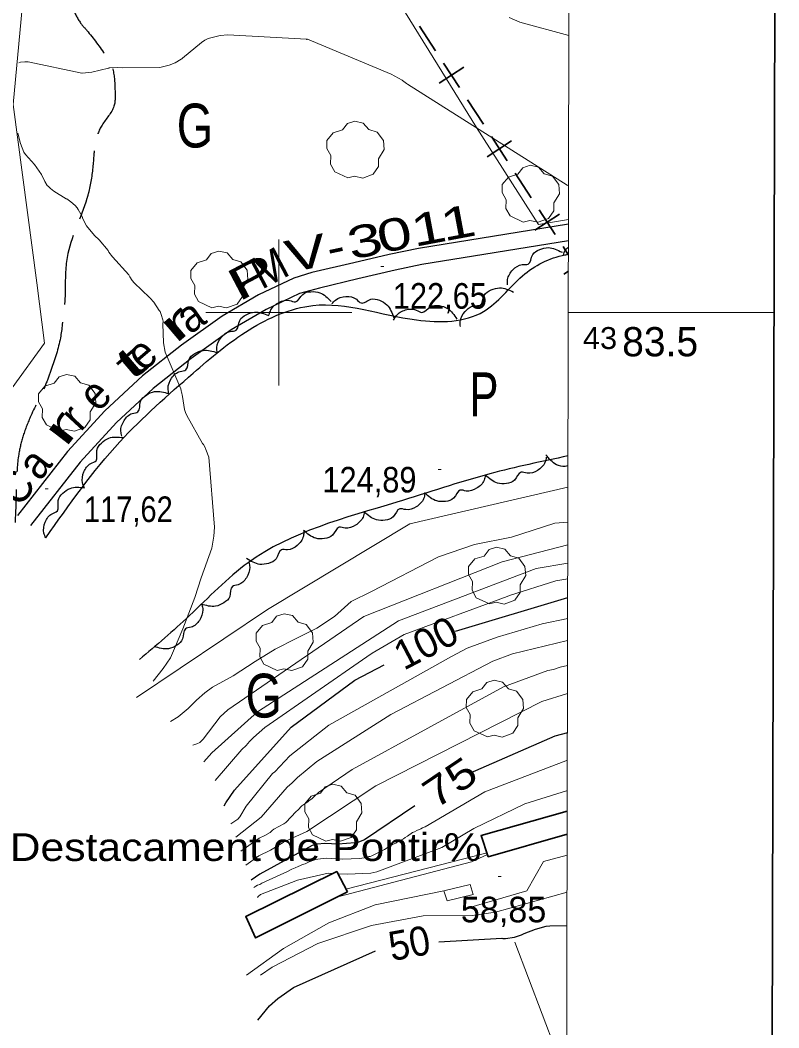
# Model space of a CAD drawing. Extents: x 480264 to 484872, y 4381275 to 4384491.
# Drawn here: x 483911.4 to 484171.3, y 4383255.2 to 4383600 of the extents above; entities that cross this region are included whole.
import ezdxf
from ezdxf.enums import TextEntityAlignment as Align

# ---------------------------------------------------------------- set-up
doc = ezdxf.new("R2010")
doc.units = 0
doc.header["$LTSCALE"] = 4
doc.linetypes.add('DOTTED', pattern=[1.5, 0.3, -1.2])
doc.linetypes.add('LONG_DASHED', pattern=[7.5, 6, -1.5])
for name, color, linetype, lineweight in [('1', 7, 'Continuous', 13), ('2', 7, 'DOTTED', 13), ('27', 7, 'Continuous', 25), ('29', 7, 'Continuous', 13), ('34', 7, 'Continuous', 35), ('36', 7, 'Continuous', 25), ('38', 7, 'Continuous', 25), ('47', 7, 'Continuous', 13), ('51', 7, 'Continuous', 13), ('7', 7, 'Continuous', 13), ('8', 7, 'Continuous', 25), ('9', 7, 'Continuous', 13)]:
    doc.layers.add(name, color=color, linetype=linetype, lineweight=lineweight)
doc.layers.add('31', color=7, linetype='Continuous')
doc.layers.add('5', color=7, linetype='Continuous')

msp = doc.modelspace()

# ---------------------------------------------------------------- linework, layer by layer
at = {"layer": '1'}
for p, q in [((484000, 4383525), (484000, 4383475)), ((483975, 4383500), (484025, 4383500)), ((484099.15, 4383500), (484169.58, 4383500))]:
    msp.add_line(p, q, dxfattribs=at)
at = {"layer": '1', "lineweight": 35}
msp.add_lwpolyline([(480452.76, 4384215.91), (484171.26, 4384207.08), (484165.43, 4381752.09), (480446.93, 4381760.92)], close=True, dxfattribs=at)
at = {"layer": '1'}
msp.add_lwpolyline([(480523.1, 4384144.4), (484100.5, 4384135.8), (484095.6, 4381823.6), (480517.1, 4381832.1)], close=True, dxfattribs=at)
at = {"layer": '27'}
for points in [[(484078.35, 4383509.47), (484078.34, 4383511.25), (484080.15, 4383514.58), (484083.37, 4383516.38), (484085.41, 4383516.59), (484086.94, 4383519.79), (484089.34, 4383521.57), (484092.3, 4383522.2), (484096.99, 4383520.59)], [(484097.47, 4383519.6), (484098.05, 4383521.28), (484099.2, 4383522.32)], [(483920.18, 4383422.86), (483945.58, 4383455.77), (483970.66, 4383479.23), (483989.85, 4383494.1), (484011.67, 4383502.39), (484047.15, 4383497.46), (484070.13, 4383500.35), (484083.46, 4383512.52), (484097.99, 4383519.71), (484099.19, 4383519.92)], [(483996.7, 4383499.2), (483997.27, 4383500.89), (484000.05, 4383503.46), (484003.68, 4383504.12), (484005.68, 4383503.66), (484008.17, 4383506.2), (484011.01, 4383507.12), (484014.01, 4383506.75), (484017.93, 4383503.71)], [(484062.19, 4383495.18), (484062.11, 4383496.95), (484063.78, 4383500.35), (484066.93, 4383502.28), (484068.96, 4383502.56), (484070.37, 4383505.83), (484072.69, 4383507.7), (484075.63, 4383508.44), (484080.37, 4383507.01)], [(484018.15, 4383502.95), (484019.37, 4383504.24), (484022.97, 4383505.43), (484026.55, 4383504.51), (484028.17, 4383503.26), (484031.49, 4383504.53), (484034.46, 4383504.18), (484037.03, 4383502.6), (484039.33, 4383498.2)], [(483978.95, 4383486.2), (483978.78, 4383487.97), (483980.28, 4383491.45), (483983.33, 4383493.53), (483985.35, 4383493.92), (483986.59, 4383497.25), (483988.82, 4383499.23), (483991.71, 4383500.12), (483996.53, 4383498.92)], [(484039.3, 4383497.32), (484040.17, 4383498.87), (484043.4, 4383500.87), (484047.09, 4383500.82), (484048.97, 4383499.98), (484051.89, 4383502), (484054.86, 4383502.35), (484057.73, 4383501.42), (484061, 4383497.69)], [(483962.35, 4383472.21), (483962.05, 4383473.96), (483963.29, 4383477.55), (483966.18, 4383479.85), (483968.17, 4383480.38), (483969.16, 4383483.8), (483971.23, 4383485.94), (483974.05, 4383487.04), (483978.94, 4383486.21)], [(483946.26, 4383457.67), (483945.89, 4383459.4), (483947, 4383463.03), (483949.8, 4383465.43), (483951.76, 4383466.04), (483952.62, 4383469.49), (483954.62, 4383471.71), (483957.39, 4383472.91), (483962.31, 4383472.26)], [(483933.44, 4383440.04), (483932.78, 4383441.69), (483933.23, 4383445.45), (483935.57, 4383448.31), (483937.4, 4383449.25), (483937.65, 4383452.79), (483939.23, 4383455.33), (483941.75, 4383456.99), (483946.7, 4383457.21)], [(484099.05, 4383450.9), (484072.28, 4383444.78), (484040.38, 4383435.09), (483989.49, 4383414.37), (483969.38, 4383396.25), (483952.24, 4383381.2)], [(484091.6, 4383450.43), (484091.16, 4383448.71), (484088.58, 4383445.93), (484085, 4383445), (484082.97, 4383445.31), (484080.69, 4383442.59), (484077.92, 4383441.47), (484074.9, 4383441.61), (484070.76, 4383444.35)], [(484099.04, 4383447.48), (484098.04, 4383447.26), (484095.09, 4383447.9), (484091.46, 4383451.29)], [(484070.77, 4383444.34), (484070.34, 4383442.61), (484067.75, 4383439.83), (484064.18, 4383438.9), (484062.15, 4383439.21), (484059.87, 4383436.49), (484057.1, 4383435.36), (484054.08, 4383435.5), (484049.94, 4383438.23)], [(483920.18, 4383422.86), (483919.52, 4383424.51), (483919.97, 4383428.27), (483922.32, 4383431.13), (483924.14, 4383432.07), (483924.39, 4383435.62), (483925.97, 4383438.15), (483928.49, 4383439.81), (483933.45, 4383440.03)], [(484050.01, 4383438.01), (484049.59, 4383436.28), (484047.04, 4383433.48), (484043.47, 4383432.52), (484041.44, 4383432.81), (484039.18, 4383430.07), (484036.43, 4383428.92), (484033.4, 4383429.03), (484029.24, 4383431.72)], [(484029.25, 4383431.71), (484028.83, 4383429.99), (484026.27, 4383427.19), (484022.71, 4383426.22), (484020.68, 4383426.51), (484018.41, 4383423.77), (484015.66, 4383422.62), (484012.64, 4383422.73), (484008.48, 4383425.43)], [(484008.54, 4383425.2), (484008.39, 4383423.43), (484006.29, 4383420.27), (484002.92, 4383418.78), (484000.86, 4383418.76), (483999.04, 4383415.7), (483996.49, 4383414.15), (483993.49, 4383413.8), (483988.97, 4383415.83)], [(483989.7, 4383414.56), (483990.04, 4383412.82), (483988.89, 4383409.2), (483986.05, 4383406.84), (483984.08, 4383406.26), (483983.17, 4383402.82), (483981.15, 4383400.63), (483978.36, 4383399.47), (483973.45, 4383400.18)], [(483973.63, 4383399.98), (483973.96, 4383398.24), (483972.79, 4383394.63), (483969.95, 4383392.28), (483967.98, 4383391.7), (483967.05, 4383388.27), (483965.02, 4383386.09), (483962.22, 4383384.94), (483957.32, 4383385.67)]]:
    msp.add_spline(points, degree=3, dxfattribs=at)
at = {"layer": '29'}
for points in [[(484023.66, 4383546.07), (484019.12, 4383548.19), (484017.71, 4383550.73), (484017.81, 4383553.71), (484016.44, 4383556.12), (484016.48, 4383558.87), (484018.64, 4383561.47), (484021.83, 4383562.47), (484023.48, 4383564.66), (484026.05, 4383565.49), (484028.91, 4383564.84), (484030.86, 4383562.57), (484033.67, 4383561.75), (484035.8, 4383558.9), (484036.04, 4383555.77), (484034.16, 4383552.62), (484034.16, 4383549.94), (484032.34, 4383547.33), (484028.72, 4383545.99), (484025.95, 4383546.62)], [(484083.72, 4383530.96), (484079.18, 4383533.08), (484077.77, 4383535.62), (484077.87, 4383538.6), (484076.5, 4383541.01), (484076.54, 4383543.76), (484078.7, 4383546.36), (484081.89, 4383547.36), (484083.54, 4383549.55), (484086.11, 4383550.38), (484088.97, 4383549.73), (484090.92, 4383547.46), (484093.73, 4383546.64), (484095.86, 4383543.79), (484096.1, 4383540.66), (484094.22, 4383537.51), (484094.22, 4383534.83), (484092.4, 4383532.22), (484088.78, 4383530.88), (484086.01, 4383531.51)], [(483977.02, 4383501.62), (483972.48, 4383503.74), (483971.07, 4383506.28), (483971.17, 4383509.26), (483969.8, 4383511.67), (483969.84, 4383514.42), (483972, 4383517.02), (483975.19, 4383518.02), (483976.84, 4383520.21), (483979.41, 4383521.04), (483982.27, 4383520.39), (483984.22, 4383518.12), (483987.03, 4383517.3), (483989.16, 4383514.45), (483989.4, 4383511.32), (483987.52, 4383508.17), (483987.52, 4383505.49), (483985.7, 4383502.88), (483982.08, 4383501.54), (483979.31, 4383502.17)], [(483924.91, 4383459.41), (483920.37, 4383461.53), (483918.96, 4383464.07), (483919.06, 4383467.05), (483917.69, 4383469.46), (483917.73, 4383472.21), (483919.89, 4383474.81), (483923.08, 4383475.81), (483924.73, 4383478), (483927.3, 4383478.83), (483930.16, 4383478.18), (483932.11, 4383475.91), (483934.92, 4383475.09), (483937.05, 4383472.24), (483937.29, 4383469.11), (483935.41, 4383465.96), (483935.41, 4383463.28), (483933.59, 4383460.67), (483929.97, 4383459.33), (483927.2, 4383459.96)], [(484072.17, 4383400.26), (484067.63, 4383402.38), (484066.22, 4383404.92), (484066.32, 4383407.9), (484064.95, 4383410.31), (484064.99, 4383413.06), (484067.15, 4383415.66), (484070.34, 4383416.66), (484071.99, 4383418.85), (484074.56, 4383419.68), (484077.42, 4383419.03), (484079.37, 4383416.76), (484082.18, 4383415.94), (484084.31, 4383413.09), (484084.55, 4383409.96), (484082.67, 4383406.81), (484082.67, 4383404.13), (484080.85, 4383401.52), (484077.23, 4383400.18), (484074.46, 4383400.81)], [(483999.4, 4383377.5), (483994.86, 4383379.62), (483993.45, 4383382.16), (483993.55, 4383385.14), (483992.18, 4383387.55), (483992.22, 4383390.3), (483994.38, 4383392.9), (483997.57, 4383393.9), (483999.22, 4383396.09), (484001.79, 4383396.92), (484004.65, 4383396.27), (484006.6, 4383394), (484009.41, 4383393.18), (484011.54, 4383390.33), (484011.78, 4383387.2), (484009.9, 4383384.05), (484009.9, 4383381.37), (484008.08, 4383378.76), (484004.46, 4383377.42), (484001.69, 4383378.05)], [(484071.41, 4383354.75), (484066.87, 4383356.87), (484065.46, 4383359.41), (484065.56, 4383362.39), (484064.19, 4383364.8), (484064.23, 4383367.55), (484066.39, 4383370.15), (484069.58, 4383371.15), (484071.23, 4383373.34), (484073.8, 4383374.17), (484076.66, 4383373.52), (484078.61, 4383371.25), (484081.42, 4383370.43), (484083.55, 4383367.58), (484083.79, 4383364.45), (484081.91, 4383361.3), (484081.91, 4383358.62), (484080.09, 4383356.01), (484076.47, 4383354.67), (484073.7, 4383355.3)], [(484016.08, 4383319.1), (484011.54, 4383321.22), (484010.13, 4383323.76), (484010.23, 4383326.74), (484008.86, 4383329.15), (484008.9, 4383331.9), (484011.06, 4383334.5), (484014.25, 4383335.5), (484015.9, 4383337.69), (484018.47, 4383338.52), (484021.33, 4383337.87), (484023.28, 4383335.6), (484026.09, 4383334.78), (484028.22, 4383331.93), (484028.46, 4383328.8), (484026.58, 4383325.65), (484026.58, 4383322.97), (484024.76, 4383320.36), (484021.14, 4383319.02), (484018.37, 4383319.65)]]:
    msp.add_lwpolyline(points, close=True, dxfattribs=at)
at = {"layer": '34'}
for p, q in [((484048.23, 4383597.95), (484053.68, 4383589.57)), ((484054.95, 4383578.46), (484063.33, 4383583.92)), ((484056.41, 4383585.38), (484061.87, 4383577)), ((484064.6, 4383572.81), (484070.06, 4383564.43)), ((484071.33, 4383553.32), (484079.71, 4383558.78)), ((484072.79, 4383560.24), (484078.25, 4383551.86)), ((484080.97, 4383547.67), (484086.43, 4383539.29)), ((484089.16, 4383535.1), (484094.62, 4383526.72)), ((484087.7, 4383528.18), (484096.08, 4383533.64)), ((484097.35, 4383522.53), (484099, 4383520)), ((484099, 4383520), (484099.19, 4383519.71)), ((484099.18, 4383514.13), (484097.6, 4383513.08))]:
    msp.add_line(p, q, dxfattribs=at)
at = {"layer": '36'}
for points in [[(484099.22, 4383530.22), (484047.89, 4383521.9), (484037.73, 4383519.8), (484025.74, 4383517), (484011.29, 4383513.64), (484005.14, 4383511.78), (483993.08, 4383506.03), (483980.57, 4383498.74), (483966.62, 4383488.78), (483953.28, 4383478.28), (483940.37, 4383466.32), (483927.64, 4383452.44), (483910.51, 4383430.56)], [(484099.2, 4383524.53), (484048.95, 4383516.38), (484039.89, 4383514.47), (484027.04, 4383511.53), (484013.95, 4383508.32), (484007.06, 4383506.47), (483995.7, 4383501.06), (483983.62, 4383494.01), (483969.99, 4383484.28), (483956.93, 4383474), (483944.36, 4383462.35), (483931.92, 4383448.81), (483914.93, 4383427.1)]]:
    msp.add_lwpolyline(points, dxfattribs=at)
at = {"layer": '38', "linetype": 'LONG_DASHED'}
msp.add_spline([(483948.27, 4383681.37), (483947.44, 4383677.16), (483943.11, 4383666.53), (483939.8, 4383660.47), (483937.44, 4383656.41), (483936.14, 4383650.27), (483939.31, 4383645.47), (483946.37, 4383638.42), (483950.03, 4383631.6), (483949.26, 4383627.51), (483946.12, 4383622.55), (483939.76, 4383618.01), (483933.67, 4383615.11), (483929.9, 4383611.7), (483929.15, 4383610.18), (483929.59, 4383603.96), (483932.34, 4383598.76), (483934.21, 4383596.54), (483940.72, 4383587.86), (483942.8, 4383584.16), (483943.86, 4383576.69), (483943.51, 4383570.58), (483939.45, 4383564.12), (483937.16, 4383558.18), (483936.44, 4383551.38), (483935.04, 4383541.91), (483934.28, 4383539.06), (483927.5, 4383518.84), (483926.82, 4383507.52), (483926.68, 4383503.83), (483926.32, 4383500.62), (483925.18, 4383491.33), (483922.04, 4383480.47), (483920.1, 4383475.28), (483915.05, 4383464.63), (483912.46, 4383457.87), (483910.9, 4383451.49), (483910.15, 4383441.41), (483909.68, 4383428.1)], degree=3, dxfattribs=at)
at = {"layer": '47', "lineweight": 35}
msp.add_lwpolyline([(484098.79, 4383329.35), (484069.28, 4383321.02), (484071.75, 4383313.76), (484098.77, 4383321.41)], dxfattribs=at)
msp.add_lwpolyline([(484023.47, 4383301.69), (484019.83, 4383308.63), (483988.65, 4383293.25), (483992.03, 4383285.97)], close=True, dxfattribs=at)
at = {"layer": '47'}
msp.add_lwpolyline([(484066.59, 4383300.86), (484065.5, 4383304.25), (484056.49, 4383302.08), (484057.61, 4383298.67)], close=True, dxfattribs=at)
at = {"layer": '51'}
for p, q in [((484071.31, 4383315.06), (484022.99, 4383302.63)), ((484080.79, 4383284.48), (484098.6, 4383237.73))]:
    msp.add_line(p, q, dxfattribs=at)
for points in [[(483986.74, 4383889), (483957.89, 4383870.69), (483913.72, 4383843.25), (483899.21, 4383834.8), (483923.65, 4383798.71), (483943.24, 4383770.31), (483969.36, 4383729.72), (483989.5, 4383693.34), (484005.24, 4383665.31), (484033, 4383619.4), (484067.74, 4383563.28), (484088.88, 4383530.13), (484099.22, 4383531.84)], [(483923.21, 4383715.44), (483915.26, 4383638.48), (483909.01, 4383571.13), (483917.15, 4383510.19), (483919.72, 4383489.5), (483897.5, 4383458.91)], [(484099.03, 4383440.24), (484044.86, 4383427.62), (483996.17, 4383398.33), (483951.24, 4383368.19)], [(484098.76, 4383314.26), (484090.68, 4383312.1), (484084.99, 4383302.04), (484065, 4383296.24), (484065, 4383296.24)], [(483988.93, 4383273.25), (484001.56, 4383282.35), (484017.09, 4383291.15), (484033.01, 4383297.29), (484056.49, 4383302.08)]]:
    msp.add_lwpolyline(points, dxfattribs=at)
at = {"layer": '7'}
for p, q in [((484034.98, 4383515.69), (484035.98, 4383515.69)), ((484054.58, 4383446.22), (484055.58, 4383446.22)), ((483919.98, 4383439.66), (483920.98, 4383439.66)), ((484075.13, 4383306.99), (484076.13, 4383306.99))]:
    msp.add_line(p, q, dxfattribs=at)
at = {"layer": '8'}
msp.add_line((484060.45, 4383390.94), (484098.95, 4383402.49), dxfattribs=at)
for points in [[(483981.32, 4383331.21), (483981.9, 4383332.22), (483984.79, 4383336.49), (484004.27, 4383358.11), (484025.98, 4383374.16), (484036.09, 4383379.46)], [(484098.85, 4383356.18), (484094.51, 4383355), (484065.57, 4383342.37)], [(484046.57, 4383331.13), (484029.38, 4383319.53), (484027.3, 4383318.72), (484026.08, 4383318.52), (484020.32, 4383318.01), (484015.76, 4383318.23), (484013.14, 4383317.99), (484011.42, 4383317.56), (483993.44, 4383307.81), (483990.57, 4383305.75)], [(484054.85, 4383284.66), (484076.4, 4383285.86), (484076.67, 4383285.79), (484076.79, 4383285.78), (484077.65, 4383285.81), (484080.71, 4383286.27), (484083.11, 4383286.98), (484084.05, 4383287.51), (484087.87, 4383289), (484091.55, 4383289.97), (484092.77, 4383290.11), (484098.71, 4383290.16)], [(483992.78, 4383257.81), (483996.83, 4383262.75), (483999.63, 4383265.24), (484004.99, 4383268.99), (484033.09, 4383281.49)]]:
    msp.add_lwpolyline(points, dxfattribs=at)
at = {"layer": '9'}
msp.add_line((484018.63, 4383308.04), (484018.62, 4383308.04), dxfattribs=at)
for points in [[(484099.35, 4383594.79), (484082.5, 4383599.34), (484078.9, 4383600.93)], [(484099.24, 4383543.31), (484098.78, 4383543.55), (484044.04, 4383578.1), (484043.76, 4383578.36), (484042.36, 4383579.36), (484042.24, 4383579.47), (484038.52, 4383581.54), (484009.86, 4383593.52), (484009.71, 4383593.52), (484009.68, 4383593.48), (484009.67, 4383593.48), (484009.66, 4383593.47), (484009.59, 4383593.47), (484009.52, 4383593.5), (484009.49, 4383593.51), (484009.44, 4383593.56), (483982.53, 4383595.02), (483979.96, 4383594.76), (483975.84, 4383593.74), (483974.65, 4383593.15), (483973.49, 4383592.41), (483967.04, 4383587.06), (483967.01, 4383587.02), (483966.83, 4383586.86), (483966.53, 4383586.65), (483964.47, 4383585.49), (483962.48, 4383584.68), (483959.23, 4383583.87), (483946.5, 4383583.73), (483944.74, 4383583.89), (483942.01, 4383583.74), (483941.83, 4383583.68), (483941.78, 4383583.63), (483941.7, 4383583.57), (483935.91, 4383582.27), (483932.58, 4383581.88), (483932.51, 4383581.86), (483932.47, 4383581.86), (483914.19, 4383585.78), (483913.02, 4383585.8), (483911.51, 4383585.64), (483910.89, 4383585.48)], [(483910.59, 4383561.42), (483911.47, 4383557.79), (483912.64, 4383554.83), (483913.19, 4383554.02), (483916.33, 4383550.6), (483918.69, 4383547.18), (483919.84, 4383544.85), (483920.7, 4383543.45)], [(483920.7, 4383543.45), (483921.07, 4383543.17), (483921.76, 4383542.44), (483922.9, 4383541.48), (483927.19, 4383538.9), (483927.3, 4383538.89), (483927.35, 4383538.87), (483928.74, 4383537.92), (483930.26, 4383536.58), (483930.92, 4383535.8), (483931.3, 4383535.23), (483932.6, 4383532.8), (483932.86, 4383532.05), (483934.08, 4383529.68), (483936.9, 4383526.4), (483938.5, 4383524.91), (483941.51, 4383521.25), (483941.82, 4383520.67), (483943, 4383519.08), (483948.67, 4383512.84), (483948.98, 4383512.24), (483949.79, 4383510.98), (483950.49, 4383510.14), (483955.74, 4383505.08), (483955.9, 4383504.98), (483955.97, 4383504.91), (483957.18, 4383503.56), (483959, 4383500.73), (483959.17, 4383500.54), (483959.33, 4383500.3), (483959.73, 4383499.31), (483960.26, 4383497.47), (483960.33, 4383496.98), (483960.33, 4383496.76), (483960.24, 4383496.23), (483960.23, 4383496.13), (483960.46, 4383489.61), (483961.02, 4383486.45), (483966.48, 4383473.91), (483966.59, 4383473.35), (483966.6, 4383473.02), (483966.61, 4383472.89), (483966.98, 4383471.27), (483966.98, 4383471.25), (483966.97, 4383471.21), (483967.7, 4383466.84), (483968, 4383465.8), (483968.48, 4383464.71), (483973.89, 4383455.18), (483974.1, 4383454.97), (483974.25, 4383454.77), (483974.92, 4383453.52), (483975.01, 4383453.11), (483976.02, 4383450.44), (483978.01, 4383426.56), (483977.72, 4383423.44)], [(484031.68, 4383404.52), (484054.64, 4383416.34), (484067.07, 4383420.65), (484079.71, 4383423.15), (484094.58, 4383427.85), (484099, 4383428.25)], [(483977.72, 4383423.44), (483977.07, 4383419.35), (483973.41, 4383409.19), (483971.18, 4383402.49), (483967.12, 4383391.72), (483964.28, 4383385.02), (483962.85, 4383381.77), (483960.42, 4383378.11), (483956.97, 4383373.85)], [(483970.54, 4383351.96), (483971.94, 4383352.37), (483972.94, 4383352.86), (483974.11, 4383353.96), (483979.93, 4383361.57), (483982.5, 4383364), (484029.1, 4383395.98), (484076.44, 4383414.7), (484098.98, 4383420.43)], [(484098.97, 4383414.19), (484088.13, 4383412.33), (484040.95, 4383394.5), (483992.74, 4383363.33), (483977.03, 4383349.28), (483974.33, 4383346.27)], [(483978.2, 4383339.81), (483987.33, 4383350.44), (483988.77, 4383351.83), (483989.94, 4383353.17), (483990.66, 4383353.82), (483991.36, 4383354.57), (483995.19, 4383358.01), (484030.18, 4383382.15), (484031.93, 4383383.37), (484042.98, 4383389.82), (484078.19, 4383402.77), (484079.05, 4383403.12), (484094.86, 4383408.18), (484098.96, 4383408.8)], [(484031.68, 4383404.52), (484024.77, 4383401.07), (484019.09, 4383395.99), (484013, 4383391.93), (484005.89, 4383388.47), (483998.79, 4383384.82), (483991.89, 4383380.55), (483984.37, 4383375.68), (483977.27, 4383371.82), (483974.63, 4383369.79), (483971.79, 4383367.35), (483968.94, 4383364.51), (483965.49, 4383361.66), (483962.85, 4383360.04)], [(483983.57, 4383325.02), (483985.96, 4383326.62), (483986.59, 4383327.37), (483988.81, 4383331.04), (483997.86, 4383342.19), (483998.64, 4383342.82), (484003.82, 4383348.24), (484017.15, 4383358.76), (484059.13, 4383382.3), (484064.48, 4383385.07), (484074.76, 4383388.94), (484090.22, 4383393.41), (484098.93, 4383395.24)], [(483985.22, 4383320.48), (483993.9, 4383327.3), (484002.8, 4383337.6), (484004.54, 4383339.01), (484006.37, 4383340.85), (484012.98, 4383346.35), (484038.37, 4383362.47), (484073.32, 4383380.69), (484079.99, 4383383.19), (484098.91, 4383387.78)], [(484098.9, 4383379.17), (484096.36, 4383378.61), (484094.03, 4383377.82), (484092.11, 4383377.46), (484076.96, 4383371.85), (484025.08, 4383343.63), (484013.56, 4383335.68), (484012.06, 4383334.39), (484011.25, 4383333.58), (484010.42, 4383332.94), (484009.92, 4383332.48), (484007.92, 4383331.11), (484006.55, 4383329.72), (484005.9, 4383329.18), (484002.42, 4383325.51), (484001.71, 4383324.99), (483998.3, 4383323.21), (483997.72, 4383322.73), (483997.31, 4383322.31), (483997.02, 4383322.07), (483995.24, 4383321), (483993.24, 4383320.05), (483986.99, 4383315.62)], [(483988.73, 4383310.84), (483993.17, 4383314.05), (483997.17, 4383315.95), (484001.52, 4383318.61), (484002.29, 4383319.06), (484009.61, 4383322.41), (484033.25, 4383338.02), (484090.04, 4383366.88), (484098.88, 4383369.65)], [(484098.83, 4383346.84), (484070.54, 4383335.95), (484050.08, 4383324), (484049.26, 4383323.62), (484048.64, 4383323.26), (484047.22, 4383322.74), (484046.46, 4383322.3), (484045.74, 4383321.98), (484044.08, 4383320.73), (484043.31, 4383320.34), (484043.23, 4383320.29), (484042.66, 4383319.85), (484042.44, 4383319.74), (484041.41, 4383319.34), (484041.14, 4383319.19), (484040.17, 4383318.49), (484040.05, 4383318.43), (484039.14, 4383318.06), (484039.05, 4383318.01), (484038.23, 4383317.47), (484037.41, 4383317.05), (484036.17, 4383316.22), (484031.9, 4383314.08), (484031.27, 4383313.87), (484030.83, 4383313.78), (484029.97, 4383313.53), (484027.58, 4383313.13), (484021.93, 4383312.9), (484016.18, 4383313.2), (484013.31, 4383312.87), (484012.31, 4383312.64), (484010.4, 4383312.02), (484008.96, 4383311.31), (484008.11, 4383311.04), (484007.41, 4383310.7), (484006.58, 4383310.4), (484005.61, 4383309.92), (484004.45, 4383309.48), (484003.02, 4383308.66), (483994.23, 4383304.67), (483993.44, 4383304.26), (483992.66, 4383303.99), (483992.15, 4383303.72), (483991.49, 4383303.25)], [(484098.81, 4383336.46), (484084.3, 4383331.88), (484066.81, 4383323.44), (484055.8, 4383316.86), (484033.56, 4383308.54), (484031.5, 4383308.07), (484023.38, 4383307.74), (484020.19, 4383307.94)], [(484020.16, 4383300.04), (484065.94, 4383312.03), (484071.5, 4383314.51)], [(484018.62, 4383308.04), (484016.91, 4383308.14), (484006.4, 4383305.73), (483993.69, 4383300.8), (483992.92, 4383300.13), (483992.73, 4383299.83)], [(483993.69, 4383273.16), (483997.67, 4383275.97), (484013.3, 4383284.03), (484031.75, 4383290.23), (484049.42, 4383293.5), (484066.2, 4383293.66), (484074.26, 4383294.72), (484098.73, 4383301.61)]]:
    msp.add_lwpolyline(points, dxfattribs=at)

# ---------------------------------------------------------------- texts
at = {"layer": '2', "width": 1.05}
msp.add_text('43', height=7.5, dxfattribs=at).set_placement((484104.14, 4383487.5))
at = {"layer": '2'}
msp.add_text('83.5', height=10, dxfattribs=at).set_placement((484117.59, 4383485))
at = {"layer": '31'}
for s, width, p in [('G', 0.8, (483971.27, 4383556.47)), ('P', 0.75, (484070.24, 4383464.5)), ('G', 0.8, (483994.84, 4383361.37))]:
    msp.add_text(s, height=15, dxfattribs=dict(at, width=width)).set_placement(p, align=Align.CENTER)
at = {"layer": '5'}
for s, rotation, width, p in [('1', 10.657, 1.45, (484052.214, 4383523.51)), ('1', 10.657, 1.45, (484062.334, 4383525.41)), ('0', 11.965, 1.45, (484040.696, 4383521.359)), ('3', 11.965, 1.45, (484030.576, 4383519.219)), ('V', 11.965, 1.45, (484010.461, 4383514.952)), ('M', 27.774, 0.95, (483999.276, 4383510.414)), ('-', 11.965, 1.25, (484020.496, 4383517.085)), ('P', 27.774, 1.65, (483993.299, 4383507.26)), ('r', 40.527, 2.15, (483968.359, 4383492.166)), ('a', 34.996, 0.95, (483972.655, 4383494.486)), ('e', 40.527, 0.95, (483956.407, 4383481.961)), ('t', 40.527, 2.15, (483952.699, 4383478.794)), ('e', 47.132, 0.95, (483940.868, 4383468.402)), ('r', 52.498, 2.05, (483929.829, 4383457.205)), ('r', 47.132, 0.95, (483933.617, 4383460.579)), ('a', 52.498, 0.95, (483920.512, 4383445.055)), ('C', 52.498, 0.95, (483914.256, 4383436.907))]:
    msp.add_text(s, height=10.99, rotation=rotation, dxfattribs=dict(at, width=width)).set_placement(p, align=Align.CENTER)
at = {"layer": '5', "width": 1.15}
msp.add_text('Destacament de Pontir%', height=9.5, dxfattribs=at).set_placement((484069.41, 4383312.29), align=Align.RIGHT)
at = {"layer": '7'}
for s, width, p in [('122,65', 0.9, (484039.05, 4383501.31)), ('124,89', 0.9, (484014.93, 4383438.4)), ('117,62', 0.85, (483933.24, 4383428.29))]:
    msp.add_text(s, height=8.75, dxfattribs=dict(at, width=width)).set_placement(p)
msp.add_text('58,85', height=8.75, dxfattribs=at).set_placement((484062.33, 4383291.29))
at = {"layer": '8'}
msp.add_text('100', height=10, rotation=27.645, dxfattribs=at).set_placement((484052.685, 4383382.507), align=Align.CENTER)
for s, rotation, width, p in [('75', 34.006, 1.25, (484061.344, 4383335.055)), ('50', 10.588, 0.95, (484045.596, 4383279.269))]:
    msp.add_text(s, height=10, rotation=rotation, dxfattribs=dict(at, width=width)).set_placement(p, align=Align.CENTER)

doc.saveas('drawing.dxf')
